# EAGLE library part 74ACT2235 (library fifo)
FIFO
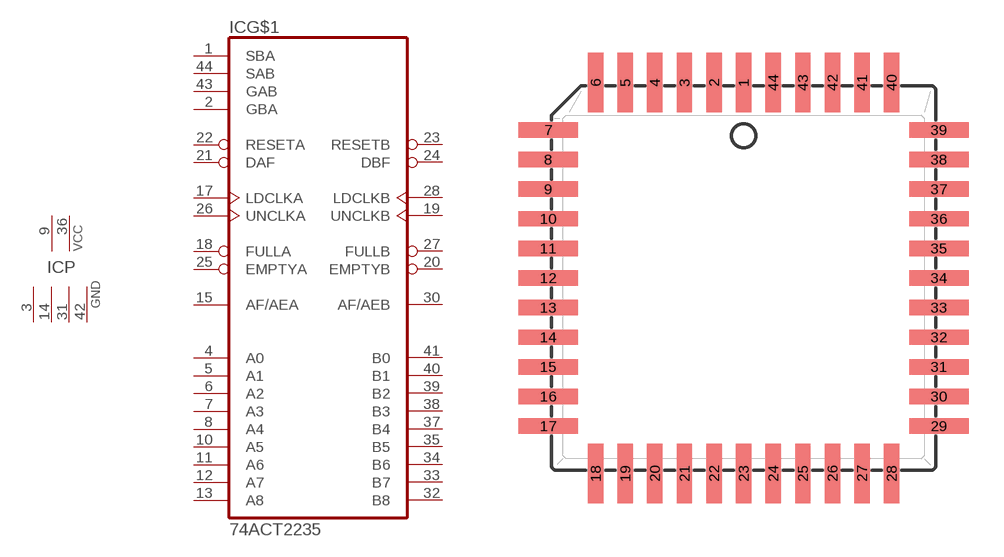
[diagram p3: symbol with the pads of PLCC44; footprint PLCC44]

Designator prefix IC; gates G$1=2235 P=2PWR4GND

## 74ACT2235 (MF: TEXAS INSTRUMENT CONNECTORS; MPN: SN74ACT2235-40FN; OC_FARNELL: unknown; OC_NEWARK: 52F2469)  [PLCC44]
1  G$1:SBA  in
2  G$1:GBA  in
3  P:GND  pwr
4  G$1:A0
5  G$1:A1
6  G$1:A2
7  G$1:A3
8  G$1:A4
9  P:VCC  pwr
10  G$1:A5
11  G$1:A6
12  G$1:A7
13  G$1:A8
14  P:GND  pwr
15  G$1:AF/AEA  out
17  G$1:LDCLKA  in
18  G$1:FULLA  out
19  G$1:UNCLKB  in
20  G$1:EMPTYB  out
21  G$1:DAF
22  G$1:RESETA
23  G$1:RESETB
24  G$1:DBF
25  G$1:EMPTYA  out
26  G$1:UNCLKA  in
27  G$1:FULLB  out
28  G$1:LDCLKB  in
30  G$1:AF/AEB  out
31  P:GND  pwr
32  G$1:B8
33  G$1:B7
34  G$1:B6
35  G$1:B5
36  P:VCC  pwr
37  G$1:B4
38  G$1:B3
39  G$1:B2
40  G$1:B1
41  G$1:B0
42  P:GND  pwr
43  G$1:GAB  in
44  G$1:SAB  in

## Footprint PLCC44 (pad centres in mm)
Plastic Leaded Carrier Package
smd 0.66 x 2.54: 1 0,8.382; 2 -1.27,8.382; 3 -2.54,8.382; 4 -3.81,8.382; 5 -5.08,8.382; 6 -6.35,8.382; 18 -6.35,-8.382; 19 -5.08,-8.382; 20 -3.81,-8.382; 21 -2.54,-8.382; 22 -1.27,-8.382; 23 0,-8.382; 24 1.27,-8.382; 25 2.54,-8.382; 26 3.81,-8.382; 27 5.08,-8.382; 28 6.35,-8.382; 40 6.35,8.382; 41 5.08,8.382; 42 3.81,8.382; 43 2.54,8.382; 44 1.27,8.382
smd 2.54 x 0.66: 7 -8.382,6.35; 8 -8.382,5.08; 9 -8.382,3.81; 10 -8.382,2.54; 11 -8.382,1.27; 12 -8.382,0; 13 -8.382,-1.27; 14 -8.382,-2.54; 15 -8.382,-3.81; 16 -8.382,-5.08; 17 -8.382,-6.35; 29 8.382,-6.35; 30 8.382,-5.08; 31 8.382,-3.81; 32 8.382,-2.54; 33 8.382,-1.27; 34 8.382,0; 35 8.382,1.27; 36 8.382,2.54; 37 8.382,3.81; 38 8.382,5.08; 39 8.382,6.35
